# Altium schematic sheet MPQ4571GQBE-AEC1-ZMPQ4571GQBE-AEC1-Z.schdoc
size 127 x 101 mm
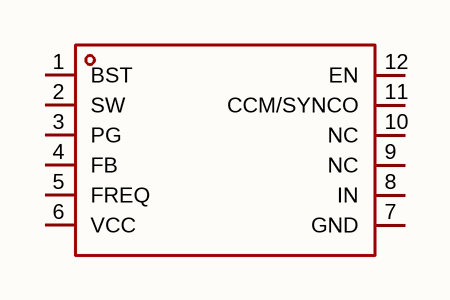
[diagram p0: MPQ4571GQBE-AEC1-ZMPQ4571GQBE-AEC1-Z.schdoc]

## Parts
U?  mpq4571gqbe-aec1-z  [QFN-12_L3.0-W2.5-P0.50-TL]  (value not drawn)

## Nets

Not connected (* = marked no-connect by the designer): U? 1(BST) 2(SW) 3(PG) 4(FB) 5(FREQ) 6(VCC) 7(GND) 8(IN) 9(NC) 10(NC) 11(CCM/SYNCO) 12(EN)

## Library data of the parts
U? = mpq4571gqbe-aec1-z: 功能类型:降压型;工作电压:4.5V~60V;输出电压:1V~54V;输出电流:1A;输出类型:可调;; Manufacturer: MPS(芯源); AddInBom: yes; ModelId: f1bfcd3610ba454abc6f8c78b2512448; ModelTransform: 99.2124,118.8974,0,0,0,0,1.475,-0.001,0; Function: 降压型; Output Voltage: 1V~54V; Output Current: 1A; Frequency - Switching: 2.2MHz; Synchronous Rectifier: 是; Number of Outputs: 1; Topology: 降压式; Quiescent Current: 40uA; Switch tube (built-in/external): 内置; Output Type: 可调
